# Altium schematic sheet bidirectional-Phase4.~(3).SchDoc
size 431 x 279 mm; Date: Not shown in title block; ApprovedBy: Not shown in title block; CheckedBy: Not shown in title block; Author: Not shown in title block; CompanyName: Not shown in title block; Engineer: Not shown in title block; Organization: Not shown in title block; Address1: Not shown in title block; Address2: Not shown in title block; Address3: Not shown in title block; Address4: Not shown in title block; DocumentNumber: 6; Revision: Use project parameter SCH_Rev; SheetNumber: 6; SheetTotal: 6; PageSetup: Record=PageOptions|CenterHorizontal=True|CenterVertical=True|PrintScale=0.96|XCorrection=1.00|YCorrection=1.00|PrintKind=0|BorderSize=5000000|LeftOffset=0|BottomOffset=0|Orientation=2|PaperLength=1000|PaperWidth=1000|Scale=100|PaperSource=15|PrintQuality=600|MediaType=1|DitherType=10|PaperKind=11x17|PrintScaleMode=1
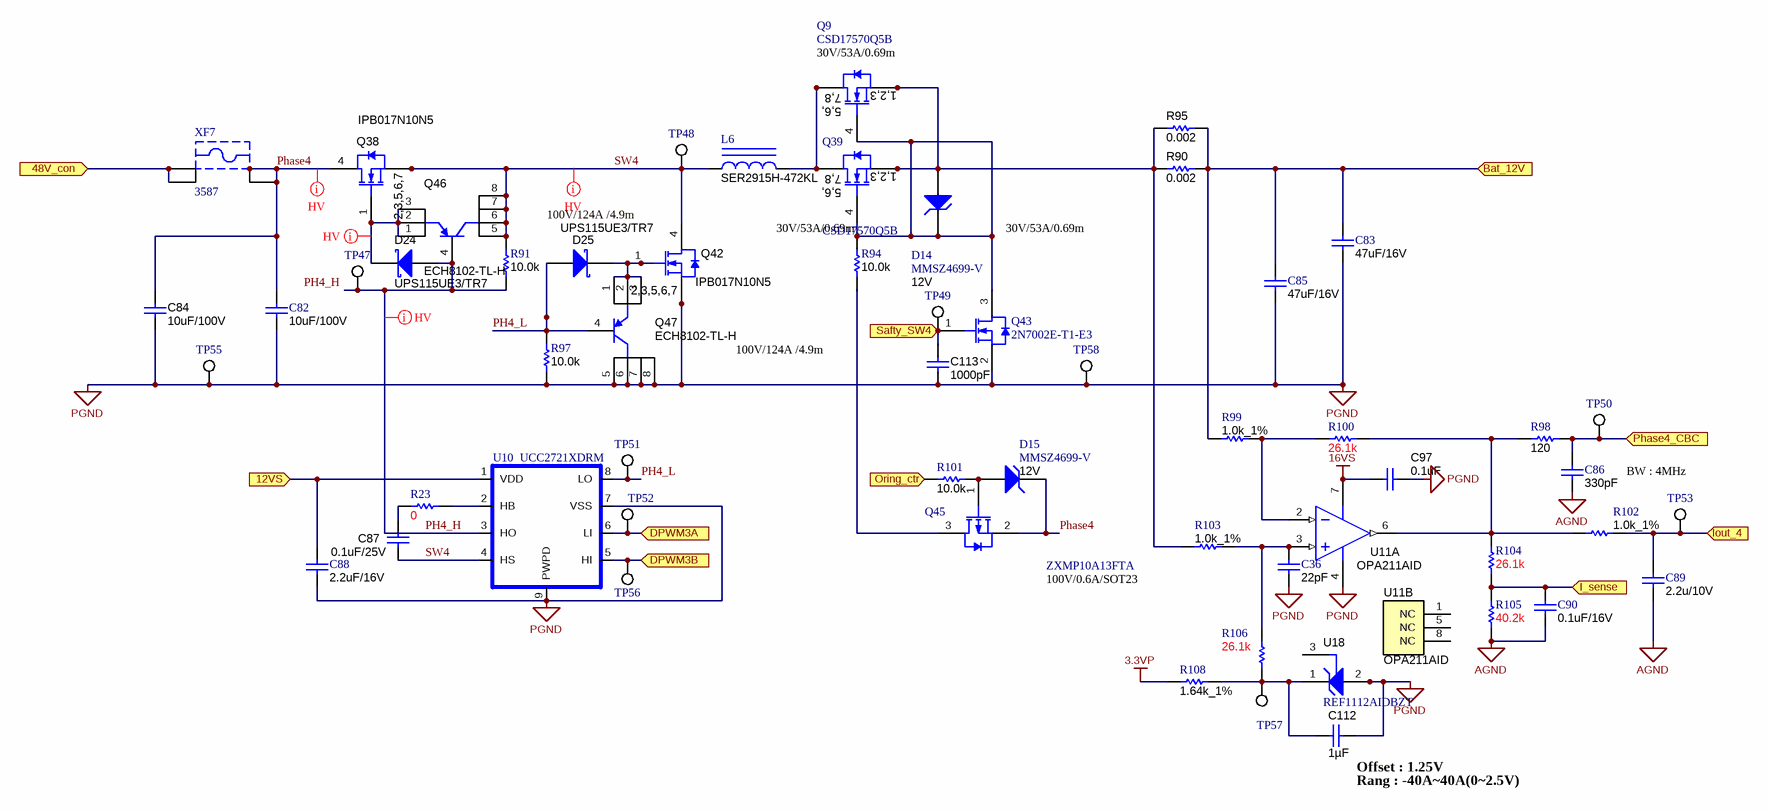
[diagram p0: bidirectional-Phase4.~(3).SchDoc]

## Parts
C36  ValueDisplayed: 22pF  [0603]  (hidden comment: 06035A220JAT2A)
C82  ValueDisplayed: 10uF/100V  [2220]  (hidden comment: C5750X7S2A106M)
C83  ValueDisplayed: 47uF/16V  [1210]  (hidden comment: GRM32ER61C476ME15L)
C84  ValueDisplayed: 10uF/100V  [2220]  (hidden comment: C5750X7S2A106M)
C85  ValueDisplayed: 47uF/16V  [1210]  (hidden comment: GRM32ER61C476ME15L)
C86  ValueDisplayed: 330pF  [0603]  (hidden comment: 06035A331JAT2A)
C87  ValueDisplayed: 0.1uF/25V  [0603]  (hidden comment: 06033C104KAT2A)
C88  ValueDisplayed: 2.2uF/16V  [0805_HV]  (hidden comment: 0805YD225KAT2A)
C89  ValueDisplayed: 2.2u/10V  [0603]  (hidden comment: C0603C225K8PACTU)
C90  ValueDisplayed: 0.1uF/16V  [0603]  (hidden comment: 0603YC104JAT2A)
C97  ValueDisplayed: 0.1uF  [0603]  (hidden comment: 06033C104JAT2A)
C112  ValueDisplayed: 1µF  [0603_095]  (hidden comment: C0603C105K3RACTU)
C113  ValueDisplayed: 1000pF  [0603]  (hidden comment: C0603X102K5RACTU)
D14  MMSZ4699-V  value 12V  [SOD-123]
D15  MMSZ4699-V  value 12V  [SOD-123]
D24  UPS115UE3/TR7  [DO-216AA]
D25  UPS115UE3/TR7  [DO-216AA]
L6  SER2915H-472KL  [SER2915H]
Q9  CSD17570Q5B  [TRANS_NexFET_Q5B]
Q38  IPB017N10N5  [DDPAK-7]
Q39  CSD17570Q5B  [TRANS_NexFET_Q5B]
Q42  IPB017N10N5  [DDPAK-7]
Q43  2N7002E-T1-E3  [SOT-23]
Q45  ZXMP10A13FTA  [SOT-23]
Q46  ECH8102-TL-H  [ECH8]
Q47  ECH8102-TL-H  [ECH8]
R23  value 0  [0603]  (hidden comment: MCR03EZPJ000)
R90  ValueDisplayed: 0.002  [2512]  (hidden comment: ERJ-M1WTF2M0U)
R91  value 10.0k  [0603]  (hidden comment: RG1608P-103-B-T5)
R94  ValueDisplayed: 10.0k  [0603]  (hidden comment: CRCW060310K0FKEA)
R95  ValueDisplayed: 0.002  [2512]  (hidden comment: ERJ-M1WTF2M0U)
R97  value 10.0k  [0603]  (hidden comment: RG1608P-103-B-T5)
R98  ValueDisplayed: 120  [0603]  (hidden comment: CRCW0603120RJNEA)
R99  value 1.0k_1%  [0603]  (hidden comment: CRCW06031K00JNEA)
R100  value 26.1k  [0603]  (hidden comment: CRCW060326K1FKEA)
R101  ValueDisplayed: 10.0k  [0603]  (hidden comment: CRCW060310K0FKEA)
R102  value 1.0k_1%  [0603]  (hidden comment: CRCW06031K00JNEA)
R103  value 1.0k_1%  [0603]  (hidden comment: CRCW06031K00JNEA)
R104  value 26.1k  [0603]  (hidden comment: CRCW060326K1FKEA)
R105  value 40.2k  [0603]  (hidden comment: CRCW060340K2FKEA)
R106  value 26.1k  [0603]  (hidden comment: CRCW060326K1FKEA)
R108  value 1.64k_1%  [0603]  (hidden comment: CRCW06031K65FKEA)
TP47  5002  [Keystone5002]  (value not drawn)
TP48  5002  [Keystone5002]  (value not drawn)
TP49  5002  [Keystone5002]  (value not drawn)
TP50  5002  [Keystone5002]  (value not drawn)
TP51  5002  [Keystone5002]  (value not drawn)
TP52  5002  [Keystone5002]  (value not drawn)
TP53  5002  [Keystone5002]  (value not drawn)
TP55  5002  [Keystone5002]  (value not drawn)
TP56  5002  [Keystone5002]  (value not drawn)
TP57  5002  [Keystone5002]  (value not drawn)
TP58  5002  [Keystone5002]  (value not drawn)
U10  UCC2721XDRM  [DRM0008A]
U11  OPA211AID  [D0008A_N]  (parts A,B of 2)
U18  REF1112AIDBZT  [DBZ0003A_N]
XF7  3587  [KEYSTONE_3587]

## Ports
12VS, 48V_con, Bat_12V, DPWM3A, DPWM3B, I_sense, Iout_4, Oring_ctr, Phase4_CBC, Safty_SW4

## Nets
3.3VP: R108.1
16VS: C97.2 U11.7(V+)
AGND: C86.2 C89.2 C90.2 R105.1
PGND: C36.2 C82.2 C83.2 C84.2 C85.2 C88.2 C97.1 C112.1 C113.2 Q42.2(S) Q42.3(S) Q42.5(S) Q42.6(S) Q42.7(S) Q43.2(S) Q47.5(C) Q47.6(C) Q47.7(C) Q47.8(C) R97.1 TP55.1 TP58.1 U10.7(VSS) U10.9(PWPD) U11.4(V-) U18.2(GND)
12VS: C88.1 U10.1(VDD) ; port 12VS
48V_con: XF7.1 XF7.2 ; port 48V_con
Bat_12V: C83.1 C85.1 R90.2 R95.2 R99.1 ; port Bat_12V
DPWM3A: TP52.1 U10.6(LI) ; port DPWM3A
DPWM3B: TP56.1 U10.5(HI) ; port DPWM3B
I_sense: C90.1 R104.1 R105.2 ; port I_sense
Iout_4: C89.1 R102.2 TP53.1 ; port Iout_4
Oring_ctr: R101.2 ; port Oring_ctr
PH4_H: D24.2(A) Q46.4(B) R91.1 TP47.1 U10.3(HO)
PH4_L: D25.2(A) Q47.4(B) R97.2 TP51.1 U10.8(LO)
Phase4: C82.1 C84.1 D15.1(K) Q38.4(D) Q45.2(S) XF7.3 XF7.4
Phase4_CBC: C86.1 R98.2 TP50.1 ; port Phase4_CBC
Safty_SW4: C113.1 Q43.1(G) TP49.1 ; port Safty_SW4
SW4: C87.2 L6.1 Q38.2(S) Q38.3(S) Q38.5(S) Q38.6(S) Q38.7(S) Q42.4(D) Q46.5(C) Q46.6(C) Q46.7(C) Q46.8(C) R91.2 TP48.1 U10.4(HS)
NetC36_1: C36.1 R103.2 R106.2 U11.3(IN+)
NetC87_1: C87.1 R23.1
NetC112_2: C112.2 R106.1 R108.2 TP57.1 U18.1(VO)
NetD14_1: D14.1(K) Q9.4(G) Q39.4(G) Q43.3(D) R94.2
NetD14_2: D14.2(A) Q9.1(S) Q9.2(S) Q9.3(S) Q39.1(S) Q39.2(S) Q39.3(S) R90.1 R95.1 R103.1
NetD15_2: D15.2(A) Q45.1(G) R101.1
NetD24_1: D24.1(K) Q38.1(G) Q46.1(E) Q46.2(E) Q46.3(E)
NetD25_1: D25.1(K) Q42.1(G) Q47.1(E) Q47.2(E) Q47.3(E)
NetL6_2: L6.2 Q9.5(D) Q9.6(D) Q9.7(D) Q9.8(D) Q39.5(D) Q39.6(D) Q39.7(D) Q39.8(D)
NetQ45_3: Q45.3(D) R94.1
NetR23_2: R23.2 U10.2(HB)
NetR98_1: R98.1 R100.2 R102.1 R104.2 U11.6(OUT)
NetR99_2: R99.2 R100.1 U11.2(IN-)

Not connected (* = marked no-connect by the designer): U11 1(NC) 5(NC) 8(NC); U18 3(NC)

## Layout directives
net class HV: NetD24_1, PH4_H, Phase4, SW4

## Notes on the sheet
- (near Q9) 30V/53A/0.69m
- 100V/124A /4.9m
- (near R94) 30V/53A/0.69m
- 30V/53A/0.69m
- BW : 4MHz
- 100V/0.6A/SOT23
- (near C112) Offset : 1.25V
- (near C112) Rang : -40A~40A(0|.5V)
- Labels drawn without touching a wire or pin: PH4_H

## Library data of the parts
C36 = 06035A220JAT2A: CAP, CERM, 22pF, 50V, +/-5%, C0G/NP0, 0603; Manufacturer: AVX; Polarized: N; CompType: Capacitor; U/M: EA; Cap_F: 0.000000000022; Tolerance_%: 5; ESR_Ohm: 0.259; Value1: 0.259 ohm; VDC_V: 50; TaMin_C: -55; TaMax_C: 125
C82 C84 = C5750X7S2A106M: CAP, CERM, 10uF, 100V, +/-20%, X7S, 2220; Manufacturer: TDK; Polarized: N; CompType: Capacitor; U/M: EA; Cap_F: 0.00001; Tolerance_%: 20; ESR_Ohm: 0.005; Value1: 0.005 ohm; VDC_V: 100; IRMS_A: 6.45; TaMin_C: -55; TaMax_C: 125
C83 C85 = GRM32ER61C476ME15L: CAP, CERM, 47uF, 16V, +/-20%, X5R, 1210; Manufacturer: MuRata; Polarized: N; CompType: Capacitor; U/M: EA; Cap_F: 0.000047; Tolerance_%: 20; ESR_Ohm: 0.002; Value1: 0.002 ohm; VDC_V: 16; TaMin_C: -55; TaMax_C: 85
C86 = 06035A331JAT2A: CAP, CERM, 330pF, 50V, +/-5%, C0G/NP0, 0603; Manufacturer: AVX; Polarized: N; CompType: Capacitor; U/M: EA; Cap_F: 0.00000000033; Tolerance_%: 5; ESR_Ohm: 0.071; Value1: 0.071 ohm; VDC_V: 50; TaMin_C: -55; TaMax_C: 125
C87 = 06033C104KAT2A: CAP, CERM, 0.1uF, 25V, +/-10%, X7R, 0603; Manufacturer: AVX; Polarized: N; CompType: Capacitor; U/M: EA; Cap_F: 0.0000001; Tolerance_%: 10; ESR_Ohm: 0.05; Value1: 0.05 ohm; VDC_V: 25; TaMin_C: -55; TaMax_C: 125
C88 = 0805YD225KAT2A: CAP, CERM, 2.2uF, 16V, +/-10%, X5R, 0805; Manufacturer: AVX; Polarized: N; CompType: Capacitor; U/M: EA; Cap_F: 0.0000022; Tolerance_%: 10; ESR_Ohm: 0.009; Value1: 0.009 ohm; VDC_V: 16; TaMin_C: -55; TaMax_C: 85; Cap_Case: 0805
C89 = C0603C225K8PACTU: CAP, CERM, 2.2uF, 10V, +/-10%, X5R, 0603; Manufacturer: Kemet; Polarized: N; CompType: Capacitor; U/M: EA; Cap_F: 0.0000022; Tolerance_%: 10; Value1: Unknown; TaMin_C: -55; TaMax_C: 85
C90 = 0603YC104JAT2A: CAP, CERM, 0.1uF, 16V, +/-5%, X7R, 0603; Manufacturer: AVX; Polarized: N; CompType: Capacitor; U/M: EA; Cap_F: 0.0000001; Tolerance_%: 5; ESR_Ohm: 0.039; Value1: 0.039 ohm; VDC_V: 16; TaMin_C: -55; TaMax_C: 125
C97 = 06033C104JAT2A: CAP, CERM, 0.1uF, 25V, +/-5%, X7R, 0603; Manufacturer: AVX; Polarized: N; CompType: Capacitor; U/M: EA; Cap_F: 0.0000001; Tolerance_%: 5; ESR_Ohm: 0.05; Value1: 0.05 ohm; VDC_V: 25; TaMin_C: -55; TaMax_C: 125
C112 = C0603C105K3RACTU: CAP, CERM, 1 µF, 25 V, +/- 10%, X7R, 0603_095; Manufacturer: Kemet; Polarized: N; CompType: Capacitor; Value: 1uF; U/M: EA; Cap_F: 0.000001; Tolerance_%: 10; Value1: Unknown; VDC_V: 25; Value2: 25V; TaMin_C: -55; TaMax_C: 125; Cap_Case: 0603
C113 = C0603X102K5RACTU: CAP, CERM, 1000 pF, 50 V, +/- 10%, X7R, 0603; Manufacturer: Kemet; Polarized: N; CompType: Capacitor; Value: 1000pF; U/M: EA; Cap_F: 0.000000001; Tolerance_%: 10; Value1: Unknown; VDC_V: 50; Value2: 50V; TaMin_C: -55; TaMax_C: 125
D14 D15 = MMSZ4699-V: Diode, Zener, 12V, 500mW, SOD-123; Manufacturer: Vishay-Semiconductor; SymbolCreator: a0412235; U/M: EA; Power_W: 0.5; Vz_V: 12; Value1: 0.5W; RJA_CperW: 67
D24 D25 = UPS115UE3/TR7: Diode, Schottky, 15 V, 1 A, DO-216-AA; Manufacturer: Microsemi; U/M: EA; Vf_V: 0.31; Value: 15V; Value1: 1A; Value2: 0.31V; Io_A: 1; Vr_V: 15; TJmax_C: 100
L6 = SER2915H-472KL: Inductor, Shielded E Core, Ferrite, 4.7 µH, 30 A, 0.00186 ohm, SMD; Manufacturer: Coilcraft; Value: 4.7uH; Ind_H: 4.7E-6; ValueDisplayed: 4.7µH; Imax_A: 30; Irms: 30A @ 40C rise; Isat: 50.1A @ 30% inductance drop; Value2: 30A
Q9 Q39 = CSD17570Q5B: MOSFET, N-CH, 30V, 51A, SON 5x6mm; Manufacturer: Texas Instruments; Alternate Manufacturer: None; U/M: EA; ChType: N; VdsMax_V: 30; Value1: 0.0076 ohm; Rdson45_Ohm: 0.0076; Value2: 97 nC; QgTyp_nC: 97; Vgs_V: 20; IdsMax_A: 51
Q38 Q42 = IPB180N08S402ATMA1: MOSFET, N-CH, 80 V, 180 A, DDPAK-7; Manufacturer: Infineon Technologies; Alternate Manufacturer: None; SymbolCreator: a0412235; U/M: EA; ChType: N; Value: 80V; VdsMax_V: 80; Value1: ? ohm; Value2: 128 nC; QgTyp_nC: 128; Vgs_V: 20; IdsMax_A: 180
Q43 = 2N7002E-T1-E3: MOSFET, N-CH, 60V, 0.24A, SOT-23; Manufacturer: Vishay-Siliconix; Alternate Manufacturer: None; U/M: EA; ChType: N; VdsMax_V: 60; Value1: 1.8 ohm; Rdson45_Ohm: 1.8; Value2: 0.4 nC; QgTyp_nC: 0.4; Vgs_V: 20; IdsMax_A: 0.24
Q45 = ZXMP10A13FTA: MOSFET, P-CH, -100V, -0.6A, SOT-23; Manufacturer: Diodes Inc.; Alternate Manufacturer: None; U/M: EA; ChType: P; VdsMax_V: -100; Value1: 1 ohm; Rdson45_Ohm: 1; Value2: 3.5 nC; QgTyp_nC: 3.5; Vgs_V: -4; IdsMax_A: -0.6
Q46 Q47 = ECH8102-TL-H, ON Semiconductor: Transistor, PNP, 30 V, 12 A, SMD-8; CompType: BJT; PNP: 1; NPN: 0; Vceo_V: 30; Vcesat1_V: 0.08; Value: 30 V; IcRated_A: 12; Value1: 12 A; HfeMax: 560; TaMin_C: -55; TaMax_C: 150; U/M: EA
R23 = MCR03EZPJ000: RES, 0 ohm, 5%, 0.1W, 0603; Manufacturer: Rohm; CompType: Resistor; Value_Code: 0000; Tolerance_%: 5; Power_W: 0.1; VDC_V: 50; TempCo: 400 ppm/C; EIA_Code: E24; U/M: EA
R90 R95 = ERJ-M1WTF2M0U: RES, 0.002, 1%, 1 W, 2512; Manufacturer: Panasonic; CompType: Resistor; Value: 0.002; Value_Code: 2L000; Tolerance_%: 1; Value2: 1W; TempCo: ppm/C; U/M: EA
R91 R97 = RG1608P-103-B-T5: RES, 10.0k ohm, 0.1%, 0.1W, 0603; Manufacturer: Susumu Co Ltd; CompType: Resistor; Res_ohm: 10000; Value_Code: 10k0; Tolerance_%: 0.1; VDC_V: 75; TempCo: 25 ppm/C; EIA_Code: E192; U/M: EA
R94 R101 = CRCW060310K0FKEA: RES, 10.0 k, 1%, 0.1 W, 0603; Manufacturer: Vishay-Dale; CompType: Resistor; Value: 10.0k; Res_ohm: 10000; Value_Code: 10k0; Tolerance_%: 1; Power_W: 0.1; Value2: 0.1W; VDC_V: 75; TempCo: 100 ppm/C; EIA_Code: E96; U/M: EA
R98 = CRCW0603120RJNEA: RES, 120, 5%, 0.1 W, 0603; Manufacturer: Vishay-Dale; CompType: Resistor; Value: 120; Value_Code: 120R; Tolerance_%: 5; Power_W: 0.1; Value2: 0.1W; VDC_V: 75; TempCo: 200 ppm/C; EIA_Code: E24; U/M: EA
R99 R102 R103 = CRCW06031K00JNEA: RES, 1.0k ohm, 5%, 0.1W, 0603; Manufacturer: Vishay-Dale; CompType: Resistor; Res_ohm: 1000; Value_Code: 1k00; Tolerance_%: 5; Power_W: 0.1; VDC_V: 75; TempCo: 200 ppm/C; EIA_Code: E24; U/M: EA
R100 R104 R106 = CRCW060326K1FKEA: RES, 26.1k ohm, 1%, 0.1W, 0603; Manufacturer: Vishay-Dale; CompType: Resistor; Res_ohm: 26100; Value_Code: 26k1; Tolerance_%: 1; Power_W: 0.1; VDC_V: 75; TempCo: 100 ppm/C; EIA_Code: E96; U/M: EA
R105 = CRCW060340K2FKEA: RES, 40.2k ohm, 1%, 0.1W, 0603; Manufacturer: Vishay-Dale; CompType: Resistor; Res_ohm: 40200; Value_Code: 40k2; Tolerance_%: 1; Power_W: 0.1; VDC_V: 75; TempCo: 100 ppm/C; EIA_Code: E96; U/M: EA
R108 = CRCW06031K65FKEA: RES, 1.65k ohm, 1%, 0.1W, 0603; Manufacturer: Vishay-Dale; CompType: Resistor; Res_ohm: 1650; Value_Code: 1k65; Tolerance_%: 1; Power_W: 0.1; VDC_V: 75; TempCo: 100 ppm/C; EIA_Code: E96; U/M: EA
TP47-TP53 TP55-TP58 = 5002: Test Point, Miniature, White, TH; Manufacturer: Keystone; CompType: Test Point Loop; U/M: EA
U10 = UCC2721XDRM: IC, 120V Boot, 4A Peak, High Frequency High-Side Low-Side Driver; Manufacturer: TI; Alternate Manufacturer: None; Area: 41800
U11 = OPA211AID: 1.1 nV/rtHz Noise, Low Power, Precision Operational Amplifier, 4.5 to 36 V, -40 to 125 degC, 8-pin SOIC (D0008A), Green (RoHS & no Sb/Br); Manufacturer: Texas Instruments; Alternate PartNumber: Equivalent; CMRR(Min)(dB): 114; GBW(Typ)(MHz): 45; IIB(Max)(pA): 175000; Iq per channel(Max)(mA): 4.5; Number of Channels: 1; Offset Drift(Typ)(uV/C): 0.15; Packing: TUBE; Rating: Catalog; Slew Rate(Typ)(V/us): 27; Sub Family: High Supply Voltage Amplifier (>=30V), Low Noise Amp (<=10nV/rtHz), Low Offset Voltage Amplifier (<=500uV), Precision Amplifier; Total Supply Voltage(Max)(+5V is 5, +/-5V is 10): 36; Vio (25C)(Max)(mV): 0.125
U18 = REF1112AIDBZt: 1 uA Shunt Voltage Reference, 1.25 V, 10 ppm / degC, 5 mA, -40 to 85 degC, 3-pin SOT-23 (DBZ), Green (RoHS & no Sb/Br); Manufacturer: Texas Instruments; Alternate PartNumber: Equivalent; Initial Accuracy @ 25/deg C(%): 0.2; Iout/Iz(Max)(mA): 5; Min Iz for Regulation(uA): 1.2; Rating: Catalog; Temp Coeff(Max)(ppm/ degree C): 50; Temp Coeff(Typ)(ppm/ degree C): 10; VO(V): 1.25
XF7 = 3587: FuseHolder; Manufacturer: Keystone; SymbolCreator: a0799628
